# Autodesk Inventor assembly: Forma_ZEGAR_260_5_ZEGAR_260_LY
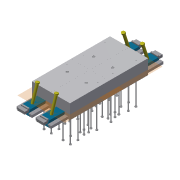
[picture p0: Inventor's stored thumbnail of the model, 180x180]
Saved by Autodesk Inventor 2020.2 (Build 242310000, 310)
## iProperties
Created: 2015-01
Part Number: Forma_ZEGAR_260_5_ZEGAR_260_LY
Document SubType Name: Assembly
Designer: F.Stasiak
Catalog Web Link: www.expertbooks.pl
Manager: www.cadconsulting.pl
Company: Fabian Stasiak CAD Consulting
Author: F.Stasiak
Subject: Zbiór ćwiczeń. Autodesk Inventor 2020. Kurs Professional
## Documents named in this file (10)
- C:\2020_Kurs_Professional\R6 Formy\Komponenty\Forma_ZEGAR_260_5_ZEGAR_260_LY.iam
- C:\2020_Kurs_Professional\R6 Formy\Komponenty\Forma_ZEGAR_260_5_ZEGAR_260_PZ.iam
- C:\2020_Kurs_Professional\R6 Formy\Komponenty\Forma_ZEGAR_260_5_ZEGAR_260_CV_2.ipt
- C:\2020_Kurs_Professional\R6 Formy\Komponenty\Forma_ZEGAR_260_5_ZEGAR_260_CV_3.ipt
- C:\2020_Kurs_Professional\R6 Formy\Komponenty\Forma_ZEGAR_260_5_ZEGAR_260_CV_4.ipt
- C:\2020_Kurs_Professional\R6 Formy\Komponenty\Forma_ZEGAR_260_5_ZEGAR_260_CV_1.ipt
- C:\2020_Kurs_Professional\R6 Formy\Komponenty\Forma_ZEGAR_260_5_ZEGAR_260_CR_2.ipt
- C:\2020_Kurs_Professional\R6 Formy\Komponenty\Forma_ZEGAR_260_5_ZEGAR_260_CR_3.ipt
- C:\2020_Kurs_Professional\R6 Formy\Komponenty\Forma_ZEGAR_260_5_ZEGAR_260_CR_4.ipt
- C:\2020_Kurs_Professional\R6 Formy\Komponenty\Forma_ZEGAR_260_5_ZEGAR_260_CR_1.ipt
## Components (12 placed, 9 different names)
1. Forma_ZEGAR_260_4_ZEGAR_260_PZ:1 [sub-assembly] — Równoległy:1, Równoległy:2, Równoległy:3, Równoległy:13, Równoległy:14, Równoległy:15, Równoległy:25, Równoległy:26, Równoległy:27, Równoległy:50, Równoległy:51
2. Forma_ZEGAR_260_4_ZEGAR_260_PZ:2 [sub-assembly] — Równoległy:4, Równoległy:5, Równoległy:6, Równoległy:16, Równoległy:17, Równoległy:18, Równoległy:28, Równoległy:29, Równoległy:30, Równoległy:52, Równoległy:53
3. Forma_ZEGAR_260_4_ZEGAR_260_PZ:3 [sub-assembly] — Równoległy:7, Równoległy:8, Równoległy:9, Równoległy:19, Równoległy:20, Równoległy:21, Równoległy:31, Równoległy:32, Równoległy:33, Równoległy:54, Równoległy:55
4. Forma_ZEGAR_260_4_ZEGAR_260_PZ:4 [sub-assembly] — Równoległy:10, Równoległy:11, Równoległy:12, Równoległy:22, Równoległy:23, Równoległy:24, Równoległy:34, Równoległy:35, Równoległy:36, Równoległy:56, Równoległy:57
5. Forma_ZEGAR_260_4_ZEGAR_260_CV_1:1 — Równoległy:13, Równoległy:14, Równoległy:15
6. Forma_ZEGAR_260_4_ZEGAR_260_CV_2:1 — Równoległy:16, Równoległy:17, Równoległy:18
7. Forma_ZEGAR_260_4_ZEGAR_260_CV_3:1 — Równoległy:19, Równoległy:20, Równoległy:21
8. Forma_ZEGAR_260_4_ZEGAR_260_CV_4:1 — Równoległy:22, Równoległy:23, Równoległy:24
9. Forma_ZEGAR_260_4_ZEGAR_260_CR_1:1 — Równoległy:25, Równoległy:26, Równoległy:27, Równoległy:50, Równoległy:51
10. Forma_ZEGAR_260_4_ZEGAR_260_CR_2:1 — Równoległy:28, Równoległy:29, Równoległy:30, Równoległy:52, Równoległy:53
11. Forma_ZEGAR_260_4_ZEGAR_260_CR_3:1 — Równoległy:31, Równoległy:32, Równoległy:33, Równoległy:54, Równoległy:55
12. Forma_ZEGAR_260_4_ZEGAR_260_CR_4:1 — Równoległy:34, Równoległy:35, Równoległy:36, Równoległy:56, Równoległy:57
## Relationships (44: Flush 44)
- Równoległy:1 [Flush]: Forma_ZEGAR_260_4_ZEGAR_260_PZ:1
- Równoległy:2 [Flush]: Forma_ZEGAR_260_4_ZEGAR_260_PZ:1
- Równoległy:3 [Flush]: Forma_ZEGAR_260_4_ZEGAR_260_PZ:1
- Równoległy:4 [Flush]: Forma_ZEGAR_260_4_ZEGAR_260_PZ:2
- Równoległy:5 [Flush]: Forma_ZEGAR_260_4_ZEGAR_260_PZ:2
- Równoległy:6 [Flush]: Forma_ZEGAR_260_4_ZEGAR_260_PZ:2
- Równoległy:7 [Flush]: Forma_ZEGAR_260_4_ZEGAR_260_PZ:3
- Równoległy:8 [Flush]: Forma_ZEGAR_260_4_ZEGAR_260_PZ:3
- Równoległy:9 [Flush]: Forma_ZEGAR_260_4_ZEGAR_260_PZ:3
- Równoległy:10 [Flush]: Forma_ZEGAR_260_4_ZEGAR_260_PZ:4
- Równoległy:11 [Flush]: Forma_ZEGAR_260_4_ZEGAR_260_PZ:4
- Równoległy:12 [Flush]: Forma_ZEGAR_260_4_ZEGAR_260_PZ:4
- Równoległy:13 [Flush]: Forma_ZEGAR_260_4_ZEGAR_260_PZ:1 ↔ Forma_ZEGAR_260_4_ZEGAR_260_CV_1:1
- Równoległy:14 [Flush]: Forma_ZEGAR_260_4_ZEGAR_260_PZ:1 ↔ Forma_ZEGAR_260_4_ZEGAR_260_CV_1:1
- Równoległy:15 [Flush]: Forma_ZEGAR_260_4_ZEGAR_260_PZ:1 ↔ Forma_ZEGAR_260_4_ZEGAR_260_CV_1:1
- Równoległy:16 [Flush]: Forma_ZEGAR_260_4_ZEGAR_260_PZ:2 ↔ Forma_ZEGAR_260_4_ZEGAR_260_CV_2:1
- Równoległy:17 [Flush]: Forma_ZEGAR_260_4_ZEGAR_260_PZ:2 ↔ Forma_ZEGAR_260_4_ZEGAR_260_CV_2:1
- Równoległy:18 [Flush]: Forma_ZEGAR_260_4_ZEGAR_260_PZ:2 ↔ Forma_ZEGAR_260_4_ZEGAR_260_CV_2:1
- Równoległy:19 [Flush]: Forma_ZEGAR_260_4_ZEGAR_260_PZ:3 ↔ Forma_ZEGAR_260_4_ZEGAR_260_CV_3:1
- Równoległy:20 [Flush]: Forma_ZEGAR_260_4_ZEGAR_260_PZ:3 ↔ Forma_ZEGAR_260_4_ZEGAR_260_CV_3:1
- Równoległy:21 [Flush]: Forma_ZEGAR_260_4_ZEGAR_260_PZ:3 ↔ Forma_ZEGAR_260_4_ZEGAR_260_CV_3:1
- Równoległy:22 [Flush]: Forma_ZEGAR_260_4_ZEGAR_260_PZ:4 ↔ Forma_ZEGAR_260_4_ZEGAR_260_CV_4:1
- Równoległy:23 [Flush]: Forma_ZEGAR_260_4_ZEGAR_260_PZ:4 ↔ Forma_ZEGAR_260_4_ZEGAR_260_CV_4:1
- Równoległy:24 [Flush]: Forma_ZEGAR_260_4_ZEGAR_260_PZ:4 ↔ Forma_ZEGAR_260_4_ZEGAR_260_CV_4:1
- Równoległy:25 [Flush]: Forma_ZEGAR_260_4_ZEGAR_260_PZ:1 ↔ Forma_ZEGAR_260_4_ZEGAR_260_CR_1:1
- Równoległy:26 [Flush]: Forma_ZEGAR_260_4_ZEGAR_260_PZ:1 ↔ Forma_ZEGAR_260_4_ZEGAR_260_CR_1:1
- Równoległy:27 [Flush]: Forma_ZEGAR_260_4_ZEGAR_260_PZ:1 ↔ Forma_ZEGAR_260_4_ZEGAR_260_CR_1:1
- Równoległy:28 [Flush]: Forma_ZEGAR_260_4_ZEGAR_260_PZ:2 ↔ Forma_ZEGAR_260_4_ZEGAR_260_CR_2:1
- Równoległy:29 [Flush]: Forma_ZEGAR_260_4_ZEGAR_260_PZ:2 ↔ Forma_ZEGAR_260_4_ZEGAR_260_CR_2:1
- Równoległy:30 [Flush]: Forma_ZEGAR_260_4_ZEGAR_260_PZ:2 ↔ Forma_ZEGAR_260_4_ZEGAR_260_CR_2:1
- Równoległy:31 [Flush]: Forma_ZEGAR_260_4_ZEGAR_260_PZ:3 ↔ Forma_ZEGAR_260_4_ZEGAR_260_CR_3:1
- Równoległy:32 [Flush]: Forma_ZEGAR_260_4_ZEGAR_260_PZ:3 ↔ Forma_ZEGAR_260_4_ZEGAR_260_CR_3:1
- Równoległy:33 [Flush]: Forma_ZEGAR_260_4_ZEGAR_260_PZ:3 ↔ Forma_ZEGAR_260_4_ZEGAR_260_CR_3:1
- Równoległy:34 [Flush]: Forma_ZEGAR_260_4_ZEGAR_260_PZ:4 ↔ Forma_ZEGAR_260_4_ZEGAR_260_CR_4:1
- Równoległy:35 [Flush]: Forma_ZEGAR_260_4_ZEGAR_260_PZ:4 ↔ Forma_ZEGAR_260_4_ZEGAR_260_CR_4:1
- Równoległy:36 [Flush]: Forma_ZEGAR_260_4_ZEGAR_260_PZ:4 ↔ Forma_ZEGAR_260_4_ZEGAR_260_CR_4:1
- Równoległy:50 [Flush]: Forma_ZEGAR_260_4_ZEGAR_260_PZ:1 ↔ Forma_ZEGAR_260_4_ZEGAR_260_CR_1:1
- Równoległy:51 [Flush]: Forma_ZEGAR_260_4_ZEGAR_260_PZ:1 ↔ Forma_ZEGAR_260_4_ZEGAR_260_CR_1:1
- Równoległy:52 [Flush]: Forma_ZEGAR_260_4_ZEGAR_260_PZ:2 ↔ Forma_ZEGAR_260_4_ZEGAR_260_CR_2:1
- Równoległy:53 [Flush]: Forma_ZEGAR_260_4_ZEGAR_260_PZ:2 ↔ Forma_ZEGAR_260_4_ZEGAR_260_CR_2:1
- Równoległy:54 [Flush]: Forma_ZEGAR_260_4_ZEGAR_260_PZ:3 ↔ Forma_ZEGAR_260_4_ZEGAR_260_CR_3:1
- Równoległy:55 [Flush]: Forma_ZEGAR_260_4_ZEGAR_260_PZ:3 ↔ Forma_ZEGAR_260_4_ZEGAR_260_CR_3:1
- Równoległy:56 [Flush]: Forma_ZEGAR_260_4_ZEGAR_260_PZ:4 ↔ Forma_ZEGAR_260_4_ZEGAR_260_CR_4:1
- Równoległy:57 [Flush]: Forma_ZEGAR_260_4_ZEGAR_260_PZ:4 ↔ Forma_ZEGAR_260_4_ZEGAR_260_CR_4:1
